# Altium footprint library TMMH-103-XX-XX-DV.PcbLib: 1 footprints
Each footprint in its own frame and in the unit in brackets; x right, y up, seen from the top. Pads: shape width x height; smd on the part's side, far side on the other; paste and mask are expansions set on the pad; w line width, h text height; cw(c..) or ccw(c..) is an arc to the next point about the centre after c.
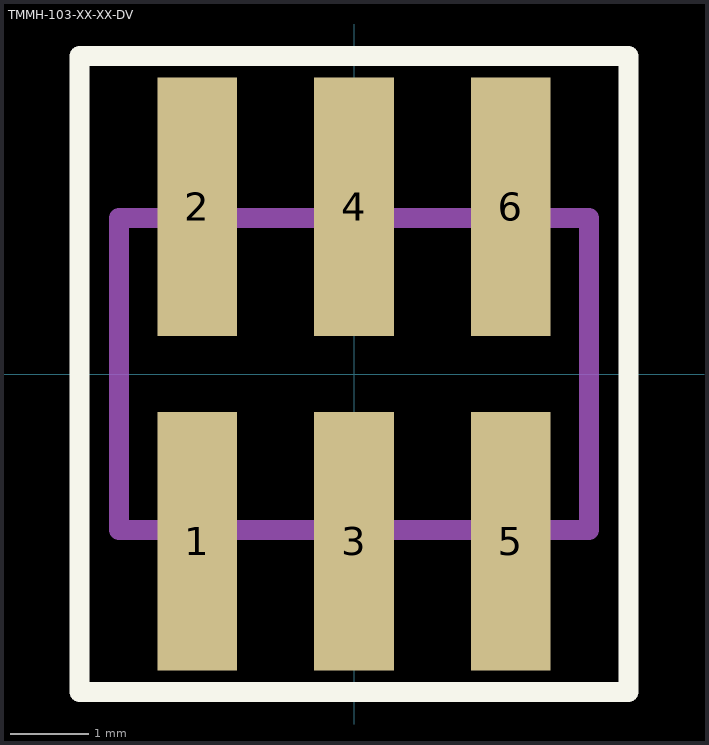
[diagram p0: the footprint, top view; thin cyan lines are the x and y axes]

## TMMH-103-XX-XX-DV [mil]
pads (6):
  rect 40x130 smd mask+2: 1(-78.74,-84) 2(-78.74,84) 3(0,-84) 4(0,84) 5(78.74,-84) 6(78.74,84)
Top Overlay:
  lines w10: -138.11,-160 138.11,-160 138.11,160 -138.11,160 -138.11,-160
Mechanical 1:
  lines w10: -118.11,-78.5 118.11,-78.5 118.11,78.5 -118.11,78.5 -118.11,-78.5
  text "J1" at -17.57,-18 h30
